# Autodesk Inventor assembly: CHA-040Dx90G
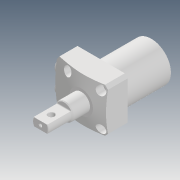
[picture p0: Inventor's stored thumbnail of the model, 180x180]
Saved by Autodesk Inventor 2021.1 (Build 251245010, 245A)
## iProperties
Created: 2019-12
Part Number: CHA-040Dx90G
Description: STEP AP203
Document SubType Name: Assembly
Designer: user
Title: CHA-040Dx90G.STEP
Revision Number: ÈÎºÎ
Sending System: SolidWorks 2017
Preprocessor: SwSTEP 2.0
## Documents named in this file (4)
- D:\Vault_2016\Projekty\Clamptek\Hydraulic\CHA\CHA\CHA-040\Inventor\CHA-040Dx90G\CHA-040Dx90G.iam
- D:\Vault_2016\Projekty\Clamptek\Hydraulic\CHA\CHA\CHA-040\Inventor\CHA-040Dx90G\CHA-040±¾Ìå.ipt
- D:\Vault_2016\Projekty\Clamptek\Hydraulic\CHA\CHA\CHA-040\Inventor\CHA-040Dx90G\CHA-040D(Ë«±Û£©»îÈû¸Ë.ipt
- D:\Vault_2016\Projekty\Clamptek\Hydraulic\CHA\CHA\CHA-040\Inventor\CHA-040Dx90G\G1-8¶ÂÍ·.ipt
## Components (4 placed, 4 different names)
1. CHA-040±¾Ìå_1
2. CHA-040D(Ë«±Û£©»îÈû¸Ë_2
3. G1-8¶ÂÍ·_3
4. G1-8¶ÂÍ·_4
